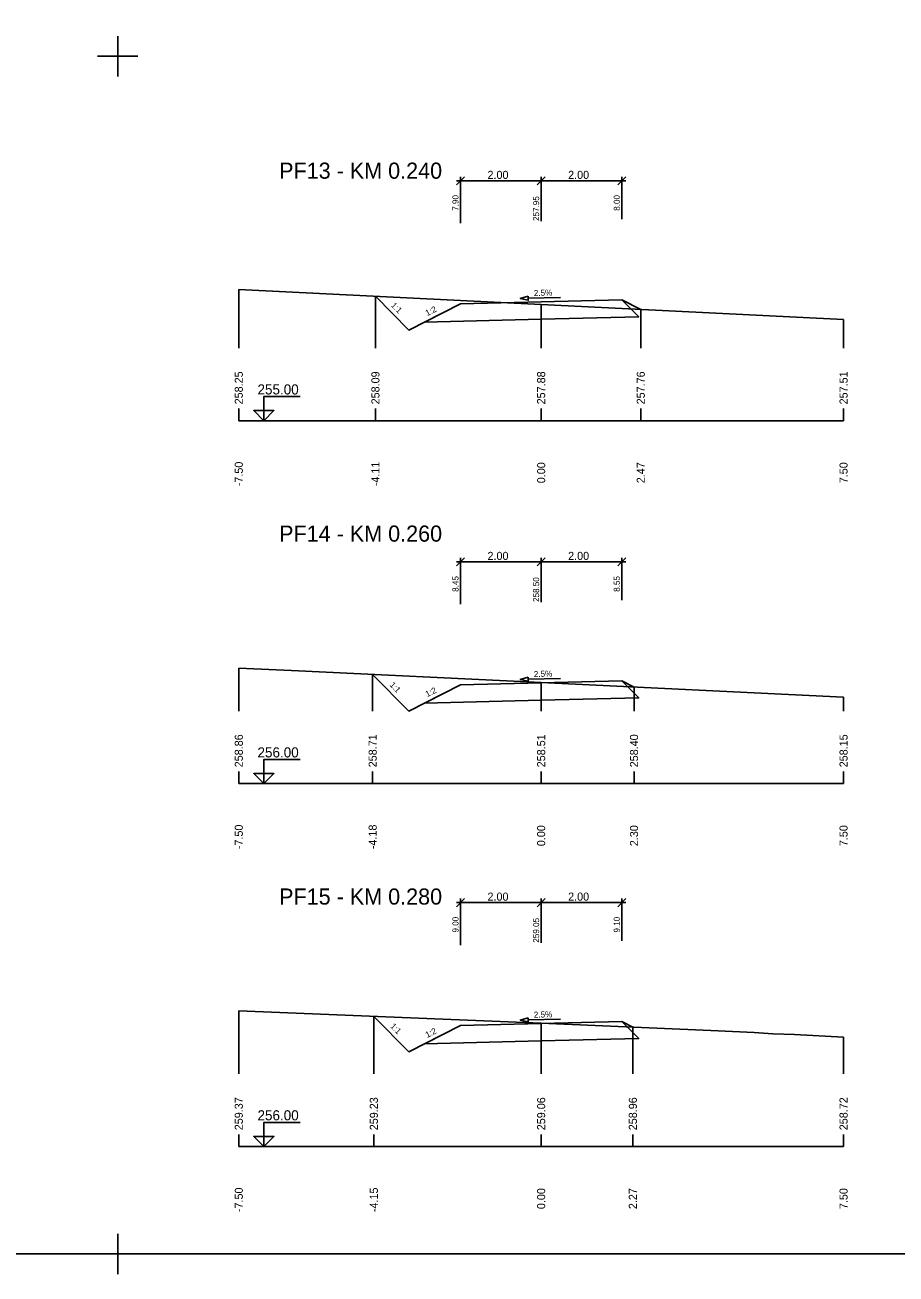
# Model space of a CAD drawing. Extents: x -5 to 1895, y -2 to 602.
# Drawn here: x 817 to 1033, y -1.6 to 308.1 of the extents above; entities that cross this region are included whole.
import ezdxf

# ---------------------------------------------------------------- set-up
doc = ezdxf.new("R2010")
doc.units = 0
for name, color, linetype in [('KOTA', 7, 'Continuous'), ('KOTA_DELKY', 7, 'Continuous'), ('KOTA_DELKY_CONT', 7, 'Continuous'), ('NS_TELESO_VOZOVKY', 7, 'Continuous'), ('NS_V_PF', 7, 'Continuous'), ('REZY_PF_PUVODNI', 7, 'Continuous'), ('SESTAVY_REZU_PF', 7, 'Continuous'), ('SKLON', 7, 'Continuous'), ('SVK', 7, 'Continuous')]:
    doc.layers.add(name, color=color, linetype=linetype)

msp = doc.modelspace()

# ---------------------------------------------------------------- linework, layer by layer
for p, q in [((840, 305.39), (840, 295.39)), ((840, 305.39), (840, 295.39)), ((840, 305.39), (840, 295.39)), ((840, 305.39), (840, 295.39)), ((840, 305.39), (840, 295.39)), ((840, 305.39), (840, 295.39)), ((840, 305.39), (840, 295.39)), ((840, 305.39), (840, 295.39)), ((840, 305.39), (840, 295.39)), ((840, 305.39), (840, 295.39)), ((840, 305.39), (840, 295.39)), ((840, 305.39), (840, 295.39)), ((840, 305.39), (840, 295.39)), ((840, 305.39), (840, 295.39)), ((840, 305.39), (840, 295.39)), ((840, 305.39), (840, 295.39)), ((840, 305.39), (840, 295.39)), ((840, 305.39), (840, 295.39)), ((840, 305.39), (840, 295.39)), ((840, 305.39), (840, 295.39)), ((840, 305.39), (840, 295.39)), ((840, 305.39), (840, 295.39)), ((840, 305.39), (840, 295.39)), ((840, 305.39), (840, 295.39)), ((840, 305.39), (840, 295.39)), ((840, 305.39), (840, 295.39)), ((840, 305.39), (840, 295.39)), ((840, 305.39), (840, 295.39)), ((840, 305.39), (840, 295.39)), ((840, 305.39), (840, 295.39)), ((845, 300.39), (835, 300.39)), ((845, 300.39), (835, 300.39)), ((845, 300.39), (835, 300.39)), ((845, 300.39), (835, 300.39)), ((845, 300.39), (835, 300.39)), ((845, 300.39), (835, 300.39)), ((845, 300.39), (835, 300.39)), ((845, 300.39), (835, 300.39)), ((845, 300.39), (835, 300.39)), ((845, 300.39), (835, 300.39)), ((845, 300.39), (835, 300.39)), ((845, 300.39), (835, 300.39)), ((845, 300.39), (835, 300.39)), ((845, 300.39), (835, 300.39)), ((845, 300.39), (835, 300.39)), ((845, 300.39), (835, 300.39)), ((845, 300.39), (835, 300.39)), ((845, 300.39), (835, 300.39)), ((845, 300.39), (835, 300.39)), ((845, 300.39), (835, 300.39)), ((845, 300.39), (835, 300.39)), ((845, 300.39), (835, 300.39)), ((845, 300.39), (835, 300.39)), ((845, 300.39), (835, 300.39)), ((845, 300.39), (835, 300.39)), ((845, 300.39), (835, 300.39)), ((845, 300.39), (835, 300.39)), ((845, 300.39), (835, 300.39)), ((845, 300.39), (835, 300.39)), ((845, 300.39), (835, 300.39)), ((840, 8.39), (840, -1.61)), ((840, 8.39), (840, -1.61)), ((840, 8.39), (840, -1.61)), ((840, 8.39), (840, -1.61)), ((840, 8.39), (840, -1.61)), ((840, 8.39), (840, -1.61)), ((840, 8.39), (840, -1.61)), ((840, 8.39), (840, -1.61)), ((840, 8.39), (840, -1.61)), ((840, 8.39), (840, -1.61)), ((840, 8.39), (840, -1.61)), ((840, 8.39), (840, -1.61)), ((845, 3.39), (835, 3.39)), ((845, 3.39), (835, 3.39)), ((845, 3.39), (835, 3.39)), ((845, 3.39), (835, 3.39)), ((845, 3.39), (835, 3.39)), ((845, 3.39), (835, 3.39)), ((845, 3.39), (835, 3.39)), ((845, 3.39), (835, 3.39)), ((845, 3.39), (835, 3.39)), ((845, 3.39), (835, 3.39)), ((845, 3.39), (835, 3.39)), ((845, 3.39), (835, 3.39))]:
    msp.add_line(p, q)
msp.add_lwpolyline([(0, 597.39), (1890, 597.39), (1890, 3.39), (0, 3.39)], close=True)
at = {"layer": 'KOTA'}
for points in [[(876.22, 212.5), (873.72, 212.5), (876.22, 210), (876.22, 216), (885.22, 216)], [(876.22, 210), (878.72, 212.5), (876.22, 212.5)], [(876.22, 122.5), (873.72, 122.5), (876.22, 120), (876.22, 126), (885.22, 126)], [(876.22, 120), (878.72, 122.5), (876.22, 122.5)], [(876.22, 32.5), (873.72, 32.5), (876.22, 30), (876.22, 36), (885.22, 36)], [(876.22, 30), (878.72, 32.5), (876.22, 32.5)]]:
    msp.add_lwpolyline(points, dxfattribs=at)
at = {"layer": 'KOTA_DELKY'}
for points in [[(924, 268.46), (926, 270.46)], [(925, 258.96), (925, 270.46)], [(944, 268.46), (946, 270.46)], [(944, 268.46), (946, 270.46)], [(945, 259.46), (945, 270.46)], [(945, 259.46), (945, 270.46)], [(964, 268.46), (966, 270.46)], [(965, 259.96), (965, 270.46)], [(924, 269.46), (946, 269.46)], [(944, 269.46), (966, 269.46)], [(924, 173.97), (926, 175.97)], [(924, 174.97), (946, 174.97)], [(925, 164.47), (925, 175.97)], [(944, 173.97), (946, 175.97)], [(944, 173.97), (946, 175.97)], [(944, 174.97), (966, 174.97)], [(945, 164.97), (945, 175.97)], [(945, 164.97), (945, 175.97)], [(964, 173.97), (966, 175.97)], [(965, 165.47), (965, 175.97)], [(924, 89.48), (926, 91.48)], [(924, 90.48), (946, 90.48)], [(925, 79.98), (925, 91.48)], [(944, 89.48), (946, 91.48)], [(944, 89.48), (946, 91.48)], [(944, 90.48), (966, 90.48)], [(945, 80.48), (945, 91.48)], [(945, 80.48), (945, 91.48)], [(964, 89.48), (966, 91.48)], [(965, 80.98), (965, 91.48)]]:
    msp.add_lwpolyline(points, dxfattribs=at)
at = {"layer": 'NS_TELESO_VOZOVKY'}
for points in [[(945, 239.46), (965, 239.96), (965, 239.96), (969.2, 235.76), (945, 235.16), (916.05, 234.43), (925, 238.96), (925, 238.96), (945, 239.46)], [(945, 144.97), (965, 145.47), (965, 145.47), (969.2, 141.27), (945, 140.67), (916.05, 139.95), (925, 144.47), (925, 144.47), (945, 144.97)], [(945, 60.48), (965, 60.98), (965, 60.98), (969.2, 56.79), (945, 56.18), (916.05, 55.46), (925, 59.98), (925, 59.98), (945, 60.48)]]:
    msp.add_lwpolyline(points, dxfattribs=at)
at = {"layer": 'NS_V_PF'}
for points in [[(903.89, 240.86), (912.19, 232.48), (925, 238.96), (925, 238.96), (945, 239.46), (965, 239.96), (965, 239.96), (969.7, 237.61)], [(903.2, 147.08), (912.19, 137.99), (925, 144.47), (925, 144.47), (945, 144.97), (965, 145.47), (965, 145.47), (968.03, 143.95)], [(903.5, 62.29), (912.19, 53.51), (925, 59.98), (925, 59.98), (945, 60.48), (965, 60.98), (965, 60.98), (967.74, 59.61)]]:
    msp.add_lwpolyline(points, dxfattribs=at)
at = {"layer": 'REZY_PF_PUVODNI'}
for points in [[(870, 242.54), (945, 238.83), (1020, 235.12)], [(870, 148.59), (883.07, 148.05), (945, 145.06), (1020, 141.45)], [(870, 63.68), (945, 60.56), (987.07, 58.81), (997.82, 58.32), (1002.46, 57.99), (1007.81, 57.78), (1020, 57.16)]]:
    msp.add_lwpolyline(points, dxfattribs=at)
at = {"layer": 'SESTAVY_REZU_PF'}
for points in [[(870, 210), (1020, 210)], [(870, 120), (1020, 120)], [(870, 30), (1020, 30)]]:
    msp.add_lwpolyline(points, dxfattribs=at)
at = {"layer": 'SKLON'}
for points in [[(941.79, 240.88), (939.8, 240.33), (941.81, 239.88), (941.79, 240.88)], [(941.8, 240.38), (949.8, 240.58)], [(941.79, 146.39), (939.8, 145.84), (941.81, 145.39), (941.79, 146.39)], [(941.8, 145.89), (949.8, 146.09)], [(941.79, 61.9), (939.8, 61.35), (941.81, 60.9), (941.79, 61.9)], [(941.8, 61.4), (949.8, 61.6)]]:
    msp.add_lwpolyline(points, dxfattribs=at)
at = {"layer": 'SVK'}
for points in [[(870, 228), (870, 242.54)], [(903.89, 228), (903.89, 240.86)], [(945, 228), (945, 238.83)], [(969.7, 228), (969.7, 237.61)], [(1020, 228), (1020, 235.12)], [(870, 210), (870, 213)], [(903.89, 210), (903.89, 213)], [(945, 210), (945, 213)], [(969.7, 210), (969.7, 213)], [(1020, 210), (1020, 213)], [(870, 138), (870, 148.59)], [(903.2, 138), (903.2, 147.08)], [(945, 138), (945, 145.06)], [(968.03, 138), (968.03, 143.95)], [(1020, 138), (1020, 141.45)], [(870, 120), (870, 123)], [(903.2, 120), (903.2, 123)], [(945, 120), (945, 123)], [(968.03, 120), (968.03, 123)], [(1020, 120), (1020, 123)], [(870, 48), (870, 63.68)], [(903.5, 48), (903.5, 62.29)], [(945, 48), (945, 60.56)], [(967.74, 48), (967.74, 59.61)], [(1020, 48), (1020, 57.16)], [(870, 30), (870, 33)], [(903.5, 30), (903.5, 33)], [(945, 30), (945, 33)], [(967.74, 30), (967.74, 33)], [(1020, 30), (1020, 33)]]:
    msp.add_lwpolyline(points, dxfattribs=at)

# ---------------------------------------------------------------- texts
at = {"layer": 'KOTA'}
for s, p in [('255.00', (874.64, 216.5)), ('256.00', (874.64, 126.5)), ('256.00', (874.64, 36.5))]:
    msp.add_text(s, height=2.5, dxfattribs=at).set_placement(p)
at = {"layer": 'KOTA_DELKY'}
for p in [(931.69, 269.96), (951.69, 269.96), (931.69, 175.47), (951.69, 175.47), (931.69, 90.98), (951.69, 90.98)]:
    msp.add_text('2.00', height=2, dxfattribs=at).set_placement(p)
at = {"layer": 'KOTA_DELKY_CONT'}
for s, p in [('7.90', (924.5, 262.05)), ('257.95', (944.5, 259.53)), ('8.00', (964.5, 262.05)), ('8.45', (924.5, 167.56)), ('258.50', (944.5, 165.05)), ('8.55', (964.5, 167.56)), ('9.00', (924.5, 83.07)), ('9.10', (964.5, 83.07)), ('259.05', (944.5, 80.56))]:
    msp.add_text(s, height=1.5, rotation=90, dxfattribs=at).set_placement(p)
at = {"layer": 'SESTAVY_REZU_PF'}
for s, p in [('PF13 - KM 0.240', (880, 270)), ('PF14 - KM 0.260', (880, 180)), ('PF15 - KM 0.280', (880, 90))]:
    msp.add_text(s, height=4, dxfattribs=at).set_placement(p)
at = {"layer": 'SKLON'}
for s, rotation, p in [('2.5%', 1.4321, (943.2, 240.91)), ('1:1', 314.7121, (907.64, 238.49)), ('1:2', 26.8233, (916.74, 235.9)), ('2.5%', 1.4321, (943.2, 146.42)), ('1:1', 314.7121, (907.3, 144.36)), ('1:2', 26.8233, (916.74, 141.41)), ('2.5%', 1.4321, (943.2, 61.94)), ('1:1', 314.7121, (907.45, 59.72)), ('1:2', 26.8233, (916.74, 56.92))]:
    msp.add_text(s, height=1.5, rotation=rotation, dxfattribs=at).set_placement(p)
at = {"layer": 'SVK'}
for s, p in [(' 258.25', (871, 213.3)), (' 258.09', (904.89, 213.3)), (' 257.88', (946, 213.3)), (' 257.76', (970.7, 213.3)), (' 257.51', (1021, 213.3)), (' -7.50', (871, 193)), (' -4.11', (904.89, 193)), ('  0.00', (946, 193)), ('  2.47', (970.7, 193)), ('  7.50', (1021, 193)), (' 258.86', (871, 123.3)), (' 258.71', (904.2, 123.3)), (' 258.51', (946, 123.3)), (' 258.40', (969.03, 123.3)), (' 258.15', (1021, 123.3)), (' -7.50', (871, 103)), (' -4.18', (904.2, 103)), ('  0.00', (946, 103)), ('  2.30', (969.03, 103)), ('  7.50', (1021, 103)), (' 259.37', (871, 33.3)), (' 259.23', (904.5, 33.3)), (' 259.06', (946, 33.3)), (' 258.96', (968.74, 33.3)), (' 258.72', (1021, 33.3)), (' -7.50', (871, 13)), (' -4.15', (904.5, 13)), ('  0.00', (946, 13)), ('  2.27', (968.74, 13)), ('  7.50', (1021, 13))]:
    msp.add_text(s, height=2, rotation=90, dxfattribs=at).set_placement(p)

doc.saveas('drawing.dxf')
